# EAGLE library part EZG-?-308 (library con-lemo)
LEMO Connector Source: http://www.lemo.com/pdfs/catalog/ROW/German/unipole_multipole.pdf
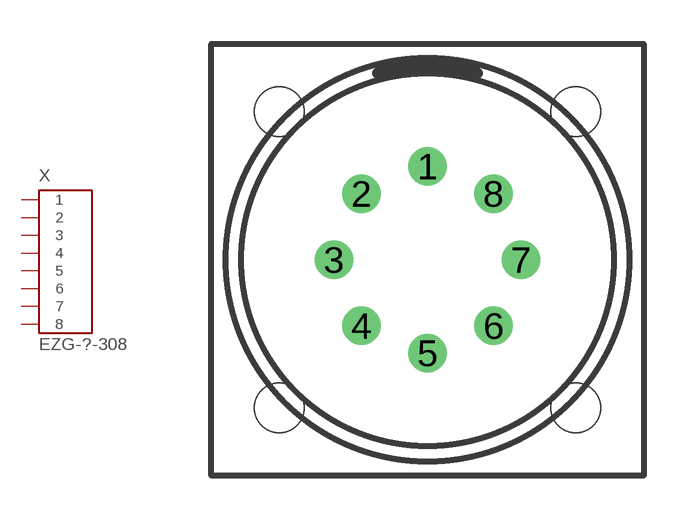
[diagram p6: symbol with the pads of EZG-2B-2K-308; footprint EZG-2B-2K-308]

Designator prefix X

## EZG-2B-308 (OC_FARNELL: unknown; OC_NEWARK: unknown)  [EZG-2B-2K-308]
1  1  pas
2  2  pas
3  3  pas
4  4  pas
5  5  pas
6  6  pas
7  7  pas
8  8  pas

## EZG-2K-308 (OC_FARNELL: unknown; OC_NEWARK: unknown)  [EZG-2B-2K-308]
Pads as for EZG-2B-2K-308

## Footprint EZG-2B-2K-308 (pad centres in mm)
LEMO Connector Source: http://www.lemo.com/pdfs/catalog/ROW/German/unipole_multipole.pdf
drill 0.8 pad 1.3 round: 1 0,3.2; 2 -2.263,2.263; 3 -3.2,0; 4 -2.263,-2.263; 5 0,-3.2; 6 2.263,-2.263; 7 3.2,0; 8 2.263,2.263
hole 1.7 at -5.08,5.08
hole 1.7 at 5.08,5.08
hole 1.7 at 5.08,-5.08
hole 1.7 at -5.08,-5.08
